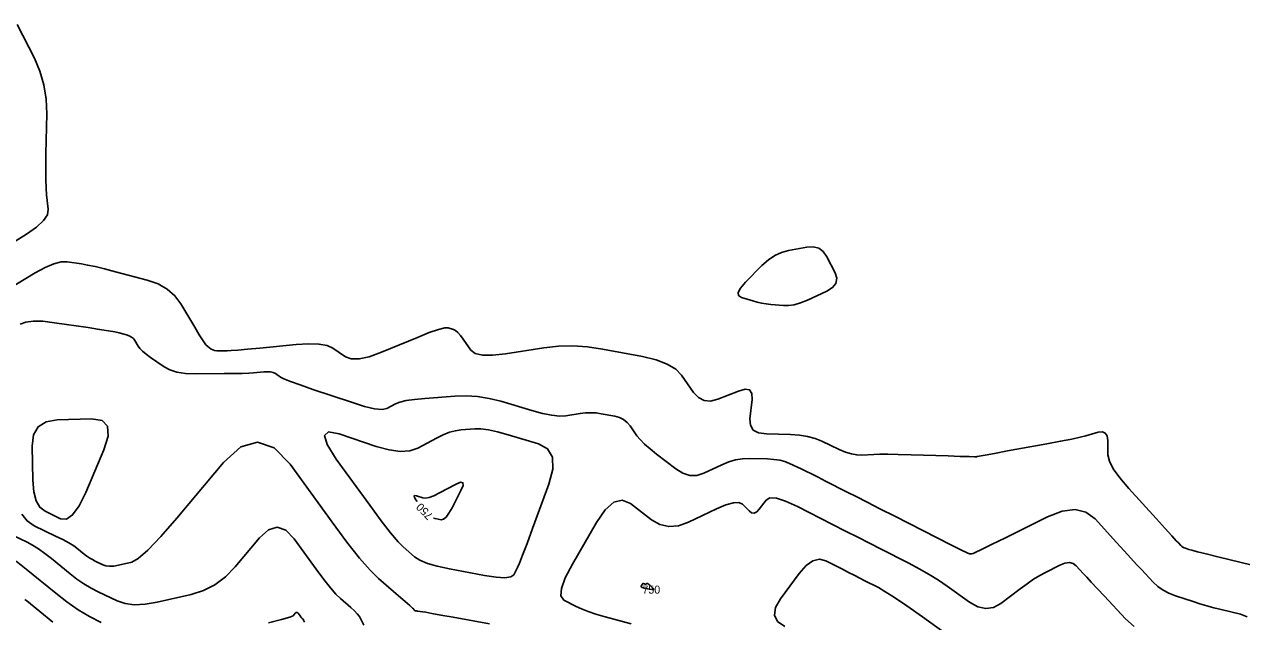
# Model space of a CAD drawing. Extents: x 2082232 to 2083549, y 592624 to 593832.
# Drawn here: x 2082625.4 to 2082731.8, y 592716.1 to 592768.3 of the extents above; entities that cross this region are included whole.
import ezdxf

# ---------------------------------------------------------------- set-up
doc = ezdxf.new("R2010")
doc.units = 0
doc.layers.add('DT_X_Contour_Major', color=7, linetype='Continuous')
doc.layers.add('DT_X_Contour_Minor', color=7, linetype='Continuous')

msp = doc.modelspace()

# ---------------------------------------------------------------- linework, layer by layer
at = {"layer": 'DT_X_Contour_Major'}
for points in [[(2082663.54, 592727.55), (2082663.73, 592728), (2082663.71, 592728.24), (2082663.49, 592728.28), (2082663.06, 592728.1), (2082661.66, 592727.35), (2082661.18, 592727.11), (2082660.77, 592726.96), (2082660.44, 592726.9), (2082660.2, 592726.92), (2082659.65, 592727.11), (2082659.49, 592727.14), (2082659.44, 592727.08), (2082659.47, 592726.95), (2082659.61, 592726.74), (2082659.71, 592726.6)], [(2082661.14, 592725.14), (2082661.28, 592725.11), (2082661.8, 592725.01), (2082662.01, 592725.05), (2082662.24, 592725.24), (2082662.49, 592725.58), (2082662.77, 592726.06), (2082663.54, 592727.55)], [(2082707.89, 592713.68), (2082703.91, 592716.51), (2082702.55, 592717.47), (2082701.46, 592718.21), (2082700.62, 592718.75), (2082700.05, 592719.08), (2082698.87, 592719.68), (2082698.42, 592719.91), (2082697.94, 592720.16), (2082697.44, 592720.41), (2082696.9, 592720.68), (2082695.45, 592721.42), (2082694.9, 592721.56), (2082694.33, 592721.42), (2082693.74, 592721), (2082693.13, 592720.31), (2082691.48, 592718.1), (2082691.04, 592717.33), (2082690.96, 592716.67), (2082691.23, 592716.12), (2082691.86, 592715.68)], [(2082680.23, 592718.9), (2082680.34, 592718.88), (2082680.39, 592718.9), (2082680.38, 592718.95), (2082680.32, 592719.03), (2082680.07, 592719.28), (2082679.98, 592719.36), (2082679.91, 592719.41), (2082679.85, 592719.44), (2082679.81, 592719.44), (2082679.72, 592719.39), (2082679.68, 592719.38), (2082679.65, 592719.38), (2082679.62, 592719.38), (2082679.59, 592719.4), (2082679.52, 592719.45), (2082679.49, 592719.46), (2082679.47, 592719.46), (2082679.44, 592719.43), (2082679.41, 592719.39), (2082679.33, 592719.25), (2082679.3, 592719.21), (2082679.29, 592719.17), (2082679.29, 592719.15), (2082679.3, 592719.13), (2082679.34, 592719.11), (2082679.36, 592719.1), (2082679.38, 592719.09), (2082679.41, 592719.09), (2082679.44, 592719.08), (2082679.52, 592719.05), (2082679.57, 592719.04), (2082679.64, 592719.02), (2082679.74, 592719), (2082679.86, 592718.98), (2082680.23, 592718.9)], [(2082625.41, 592718.04), (2082625.56, 592717.92), (2082627.84, 592716.07)]]:
    msp.add_lwpolyline(points, dxfattribs=at)
at = {"layer": 'DT_X_Contour_Minor'}
for points in [[(2082624.73, 592768.3), (2082626.23, 592765.34), (2082626.72, 592764.2), (2082627.07, 592763.01), (2082627.26, 592761.77), (2082627.31, 592760.49), (2082627.24, 592756.99), (2082627.23, 592755.78), (2082627.23, 592754.78), (2082627.26, 592753.99), (2082627.3, 592753.42), (2082627.45, 592752.16), (2082627.37, 592751.67), (2082627.03, 592751.15), (2082626.42, 592750.58), (2082625.55, 592749.98), (2082622.86, 592748.32)], [(2082688.08, 592744.44), (2082687.82, 592744.6), (2082687.79, 592744.88), (2082687.99, 592745.26), (2082688.42, 592745.76), (2082689.87, 592747.22), (2082690.43, 592747.72), (2082690.99, 592748.1), (2082691.58, 592748.38), (2082692.18, 592748.54), (2082693.79, 592748.83), (2082694.36, 592748.86), (2082694.83, 592748.73), (2082695.23, 592748.45), (2082695.54, 592748), (2082696.26, 592746.6), (2082696.41, 592746.11), (2082696.34, 592745.67), (2082696.05, 592745.3), (2082695.53, 592744.98), (2082693.84, 592744.21), (2082693.24, 592743.96), (2082692.69, 592743.8), (2082692.2, 592743.72), (2082691.75, 592743.72), (2082690.65, 592743.83), (2082690.24, 592743.88), (2082689.84, 592743.95), (2082689.46, 592744.03), (2082689.08, 592744.13), (2082688.08, 592744.44)], [(2082732.75, 592721.03), (2082729.73, 592721.77), (2082728.72, 592722.02), (2082727.97, 592722.21), (2082727.47, 592722.34), (2082727.22, 592722.4), (2082726.9, 592722.51), (2082726.79, 592722.55), (2082726.68, 592722.61), (2082726.59, 592722.68), (2082726.5, 592722.75), (2082726.29, 592722.98), (2082726.11, 592723.17), (2082725.73, 592723.6), (2082725.13, 592724.24), (2082724.34, 592725.12), (2082721.95, 592727.75), (2082721.16, 592728.67), (2082720.6, 592729.47), (2082720.26, 592730.13), (2082720.13, 592730.67), (2082720.11, 592731.93), (2082720.05, 592732.33), (2082719.89, 592732.58), (2082719.64, 592732.69), (2082719.28, 592732.65), (2082718.21, 592732.35), (2082717.69, 592732.22), (2082716.96, 592732.06), (2082715.99, 592731.87), (2082714.8, 592731.65), (2082711.34, 592731.02), (2082710.2, 592730.81), (2082709.38, 592730.66), (2082708.88, 592730.57), (2082708.7, 592730.53), (2082708.64, 592730.52), (2082708.46, 592730.52), (2082707.99, 592730.53), (2082707.22, 592730.55), (2082706.16, 592730.58), (2082702.91, 592730.68), (2082701.79, 592730.71), (2082700.88, 592730.73), (2082700.17, 592730.73), (2082699.66, 592730.71), (2082698.58, 592730.66), (2082698.16, 592730.67), (2082697.69, 592730.76), (2082697.18, 592730.92), (2082696.63, 592731.15), (2082695.11, 592731.88), (2082694.51, 592732.11), (2082693.86, 592732.29), (2082693.15, 592732.4), (2082692.38, 592732.45), (2082690.26, 592732.51), (2082689.58, 592732.6), (2082689.11, 592732.85), (2082688.86, 592733.26), (2082688.82, 592733.82), (2082689.01, 592735.52), (2082688.99, 592736.05), (2082688.78, 592736.35), (2082688.39, 592736.42), (2082687.81, 592736.26), (2082686.01, 592735.54), (2082685.37, 592735.38), (2082684.81, 592735.42), (2082684.31, 592735.68), (2082683.88, 592736.14), (2082682.84, 592737.65), (2082682.33, 592738.17), (2082681.59, 592738.62), (2082680.62, 592738.99), (2082679.43, 592739.27), (2082675.93, 592739.93), (2082674.62, 592740.12), (2082673.33, 592740.2), (2082672.06, 592740.17), (2082670.79, 592740.03), (2082667.44, 592739.51), (2082666.31, 592739.38), (2082665.43, 592739.39), (2082664.8, 592739.55), (2082664.42, 592739.84), (2082663.75, 592740.8), (2082663.5, 592741.12), (2082663.28, 592741.37), (2082663.07, 592741.54), (2082662.89, 592741.64), (2082662.42, 592741.79), (2082662.12, 592741.78), (2082661.57, 592741.64), (2082660.77, 592741.36), (2082659.73, 592740.94), (2082656.6, 592739.65), (2082655.52, 592739.26), (2082654.64, 592739.06), (2082653.94, 592739.06), (2082653.43, 592739.25), (2082652.34, 592740), (2082651.83, 592740.23), (2082651.12, 592740.36), (2082650.22, 592740.39), (2082649.13, 592740.32), (2082645.95, 592740.01), (2082644.88, 592739.91), (2082644.04, 592739.84), (2082643.44, 592739.79), (2082643.08, 592739.78), (2082642.42, 592739.77), (2082642.19, 592739.78), (2082641.99, 592739.81), (2082641.83, 592739.86), (2082641.7, 592739.93), (2082641.39, 592740.15), (2082641.23, 592740.31), (2082640.99, 592740.65), (2082640.66, 592741.16), (2082640.26, 592741.84), (2082639.05, 592743.89), (2082638.53, 592744.59), (2082637.86, 592745.17), (2082637.05, 592745.63), (2082636.09, 592745.96), (2082633.34, 592746.69), (2082632.38, 592746.93), (2082631.56, 592747.13), (2082630.88, 592747.27), (2082630.34, 592747.37), (2082629.09, 592747.55), (2082628.57, 592747.54), (2082627.93, 592747.38), (2082627.18, 592747.06), (2082626.31, 592746.58), (2082623.85, 592745.1)], [(2082624.99, 592742.09), (2082625.48, 592742.27), (2082626.14, 592742.36), (2082626.97, 592742.35), (2082627.99, 592742.23), (2082630.93, 592741.8), (2082631.93, 592741.65), (2082632.71, 592741.52), (2082633.28, 592741.42), (2082633.64, 592741.34), (2082634.3, 592741.17), (2082634.53, 592741.09), (2082634.73, 592740.98), (2082634.89, 592740.84), (2082635.01, 592740.67), (2082635.3, 592740.18), (2082635.45, 592739.98), (2082635.68, 592739.74), (2082636, 592739.48), (2082636.4, 592739.19), (2082637.57, 592738.38), (2082638.08, 592738.11), (2082638.7, 592737.92), (2082639.46, 592737.8), (2082640.33, 592737.77), (2082642.84, 592737.78), (2082643.7, 592737.78), (2082644.41, 592737.8), (2082644.98, 592737.82), (2082645.39, 592737.85), (2082646.3, 592737.94), (2082646.62, 592737.95), (2082646.89, 592737.93), (2082647.12, 592737.87), (2082647.31, 592737.78), (2082647.75, 592737.48), (2082648.05, 592737.33), (2082648.63, 592737.1), (2082649.48, 592736.79), (2082650.6, 592736.4), (2082653.96, 592735.27), (2082655.1, 592734.92), (2082655.99, 592734.71), (2082656.64, 592734.65), (2082657.05, 592734.73), (2082657.83, 592735.15), (2082658.2, 592735.29), (2082658.75, 592735.42), (2082659.48, 592735.52), (2082660.38, 592735.61), (2082663.01, 592735.81), (2082664, 592735.84), (2082665, 592735.77), (2082666, 592735.61), (2082667.02, 592735.36), (2082669.73, 592734.55), (2082670.68, 592734.3), (2082671.49, 592734.14), (2082672.17, 592734.07), (2082672.71, 592734.1), (2082673.97, 592734.29), (2082674.44, 592734.35), (2082674.9, 592734.36), (2082675.36, 592734.34), (2082675.8, 592734.27), (2082676.99, 592734.05), (2082677.41, 592733.93), (2082677.77, 592733.76), (2082678.08, 592733.52), (2082678.34, 592733.23), (2082678.94, 592732.35), (2082679.22, 592732.01), (2082679.6, 592731.62), (2082680.08, 592731.2), (2082680.65, 592730.74), (2082682.33, 592729.46), (2082682.95, 592729.07), (2082683.57, 592728.88), (2082684.18, 592728.88), (2082684.78, 592729.07), (2082686.37, 592729.82), (2082686.97, 592730.06), (2082687.56, 592730.24), (2082688.16, 592730.33), (2082688.75, 592730.35), (2082690.34, 592730.32), (2082690.91, 592730.28), (2082691.43, 592730.21), (2082691.88, 592730.09), (2082692.29, 592729.93), (2082693.29, 592729.46), (2082693.7, 592729.26), (2082694.2, 592729.01), (2082694.78, 592728.72), (2082695.44, 592728.39), (2082697.32, 592727.43), (2082698.11, 592727.03), (2082699.06, 592726.55), (2082700.19, 592725.97), (2082701.49, 592725.31), (2082705.18, 592723.43), (2082706.39, 592722.82), (2082707.27, 592722.38), (2082707.81, 592722.11), (2082708.01, 592722.03), (2082708.11, 592722.02), (2082708.14, 592722.02), (2082708.18, 592722.03), (2082708.21, 592722.03), (2082708.24, 592722.03), (2082708.33, 592722.05), (2082708.53, 592722.14), (2082709.07, 592722.4), (2082709.95, 592722.83), (2082711.16, 592723.43), (2082714.83, 592725.26), (2082716.13, 592725.76), (2082717.25, 592725.9), (2082718.21, 592725.68), (2082719, 592725.08), (2082720.88, 592723.02), (2082721.54, 592722.29), (2082722.13, 592721.65), (2082722.63, 592721.1), (2082723.06, 592720.65), (2082724.09, 592719.56), (2082724.5, 592719.18), (2082724.96, 592718.85), (2082725.47, 592718.58), (2082726.03, 592718.36), (2082727.59, 592717.85), (2082728.18, 592717.67), (2082728.79, 592717.49), (2082729.4, 592717.32), (2082730.03, 592717.16), (2082731.72, 592716.75), (2082732.32, 592716.52)], [(2082626.04, 592731.44), (2082626.16, 592732.43), (2082626.57, 592733.14), (2082627.26, 592733.57), (2082628.24, 592733.74), (2082631.24, 592733.83), (2082632.15, 592733.68), (2082632.63, 592733.18), (2082632.68, 592732.32), (2082632.31, 592731.11), (2082630.72, 592727.4), (2082630.14, 592726.21), (2082629.58, 592725.43), (2082629.04, 592725.06), (2082628.52, 592725.1), (2082627.17, 592725.75), (2082626.72, 592726.1), (2082626.39, 592726.67), (2082626.19, 592727.46), (2082626.1, 592728.47), (2082626.04, 592731.44)], [(2082665.6, 592720.14), (2082666.63, 592719.98), (2082667.39, 592719.94), (2082667.9, 592720.01), (2082668.16, 592720.19), (2082668.48, 592720.82), (2082668.66, 592721.21), (2082668.94, 592721.91), (2082669.32, 592722.92), (2082669.8, 592724.23), (2082671.24, 592728.13), (2082671.58, 592729.44), (2082671.55, 592730.47), (2082671.12, 592731.2), (2082670.32, 592731.64), (2082667.66, 592732.43), (2082666.73, 592732.69), (2082665.94, 592732.86), (2082665.28, 592732.95), (2082664.75, 592732.96), (2082663.54, 592732.86), (2082663.06, 592732.79), (2082662.55, 592732.65), (2082661.99, 592732.43), (2082661.4, 592732.14), (2082659.77, 592731.26), (2082659.08, 592731.02), (2082658.24, 592730.97), (2082657.25, 592731.11), (2082656.12, 592731.42), (2082652.88, 592732.51), (2082651.95, 592732.68), (2082651.61, 592732.37), (2082651.84, 592731.58), (2082652.64, 592730.31), (2082655.57, 592726.28), (2082656.57, 592724.92), (2082657.39, 592723.86), (2082658.04, 592723.09), (2082658.5, 592722.63), (2082659.48, 592721.78), (2082659.95, 592721.47), (2082660.61, 592721.19), (2082661.47, 592720.94), (2082662.53, 592720.71), (2082665.6, 592720.14)], [(2082666.04, 592715.9), (2082662.85, 592716.49), (2082661.79, 592716.68), (2082660.99, 592716.82), (2082660.47, 592716.92), (2082660.21, 592716.96), (2082659.75, 592717.03), (2082659.66, 592717.04), (2082659.6, 592717.05), (2082659.57, 592717.05), (2082659.52, 592717.06), (2082659.5, 592717.07), (2082659.48, 592717.08), (2082659.47, 592717.09), (2082659.46, 592717.1), (2082659.43, 592717.14), (2082659.43, 592717.16), (2082659.42, 592717.17), (2082659.41, 592717.18), (2082659.41, 592717.19), (2082659.4, 592717.21), (2082659.31, 592717.29), (2082659.07, 592717.51), (2082658.66, 592717.86), (2082658.09, 592718.35), (2082656.34, 592719.86), (2082655.6, 592720.59), (2082654.67, 592721.65), (2082653.57, 592723.05), (2082652.28, 592724.79), (2082648.6, 592729.86), (2082647.2, 592731.29), (2082645.76, 592731.8), (2082644.29, 592731.37), (2082642.77, 592730.01), (2082638.69, 592725.14), (2082637.29, 592723.53), (2082636.17, 592722.36), (2082635.32, 592721.61), (2082634.75, 592721.3), (2082633.58, 592721.03), (2082633.17, 592720.96), (2082632.8, 592720.95), (2082632.48, 592720.98), (2082632.21, 592721.07), (2082631.56, 592721.39), (2082631.32, 592721.52), (2082631.07, 592721.66), (2082630.83, 592721.83), (2082630.6, 592722.01), (2082629.96, 592722.53), (2082629.67, 592722.74), (2082629.25, 592722.98), (2082628.73, 592723.27), (2082628.08, 592723.58), (2082626.2, 592724.48), (2082625.59, 592724.9), (2082625.14, 592725.5)], [(2082722.41, 592715.68), (2082721.68, 592716.36), (2082719.83, 592718.32), (2082719.19, 592718.99), (2082718.67, 592719.55), (2082718.27, 592719.98), (2082717.97, 592720.3), (2082717.35, 592720.99), (2082717.08, 592721.18), (2082716.76, 592721.26), (2082716.37, 592721.2), (2082715.93, 592721.03), (2082714.66, 592720.4), (2082714.16, 592720.13), (2082713.63, 592719.8), (2082713.06, 592719.42), (2082712.45, 592718.97), (2082710.77, 592717.7), (2082710.12, 592717.35), (2082709.45, 592717.25), (2082708.75, 592717.4), (2082708.03, 592717.8), (2082706.06, 592719.2), (2082705.3, 592719.72), (2082704.49, 592720.23), (2082703.63, 592720.72), (2082702.72, 592721.2), (2082700.23, 592722.47), (2082699.27, 592722.96), (2082698.25, 592723.48), (2082697.18, 592724.02), (2082696.05, 592724.6), (2082692.98, 592726.16), (2082691.94, 592726.63), (2082691.14, 592726.89), (2082690.57, 592726.92), (2082690.23, 592726.73), (2082689.63, 592725.93), (2082689.41, 592725.7), (2082689.19, 592725.59), (2082688.96, 592725.62), (2082688.74, 592725.78), (2082688.16, 592726.37), (2082687.85, 592726.51), (2082687.37, 592726.49), (2082686.71, 592726.3), (2082685.89, 592725.95), (2082683.45, 592724.8), (2082682.56, 592724.48), (2082681.72, 592724.41), (2082680.94, 592724.58), (2082680.22, 592725), (2082678.36, 592726.42), (2082677.65, 592726.71), (2082676.92, 592726.54), (2082676.17, 592725.88), (2082675.39, 592724.76), (2082673.31, 592721.13), (2082672.67, 592719.92), (2082672.33, 592718.99), (2082672.29, 592718.35), (2082672.55, 592717.99), (2082673.63, 592717.42), (2082674.09, 592717.21), (2082674.67, 592716.99), (2082675.35, 592716.76), (2082676.15, 592716.53), (2082678.44, 592715.91)], [(2082624.37, 592723.62), (2082625.6, 592723.04), (2082626.08, 592722.78), (2082626.6, 592722.46), (2082627.15, 592722.07), (2082627.74, 592721.61), (2082629.35, 592720.29), (2082629.96, 592719.82), (2082630.57, 592719.4), (2082631.19, 592719.03), (2082631.81, 592718.71), (2082633.48, 592717.91), (2082634.16, 592717.68), (2082634.97, 592717.58), (2082635.91, 592717.62), (2082636.96, 592717.81), (2082639.94, 592718.47), (2082641.02, 592718.81), (2082642.02, 592719.32), (2082642.94, 592720.01), (2082643.78, 592720.88), (2082645.91, 592723.42), (2082646.7, 592724.13), (2082647.47, 592724.36), (2082648.22, 592724.09), (2082648.95, 592723.34), (2082650.88, 592720.69), (2082651.55, 592719.79), (2082652.13, 592719.06), (2082652.61, 592718.5), (2082653, 592718.12), (2082653.91, 592717.33), (2082654.22, 592717.05), (2082654.47, 592716.79), (2082654.66, 592716.55), (2082654.78, 592716.33), (2082655.04, 592715.78)], [(2082624.63, 592721.4), (2082625.51, 592720.69), (2082628.11, 592718.58), (2082629.08, 592717.82), (2082630.07, 592717.14), (2082631.06, 592716.55), (2082632.06, 592716.02)], [(2082646.71, 592716.01), (2082647.86, 592716.29), (2082648.58, 592716.49), (2082648.86, 592716.61), (2082649.05, 592716.83), (2082649.11, 592716.89), (2082649.18, 592716.91), (2082649.25, 592716.89), (2082649.31, 592716.83), (2082649.47, 592716.6), (2082649.53, 592716.52), (2082649.58, 592716.46), (2082649.62, 592716.41), (2082649.66, 592716.38), (2082649.74, 592716.31), (2082649.78, 592716.24), (2082649.87, 592716.07)]]:
    msp.add_lwpolyline(points, dxfattribs=at)

# ---------------------------------------------------------------- texts
at = {"layer": 'DT_X_Contour_Major'}
msp.add_text('750', height=0.7, rotation=134.4801, dxfattribs=at).set_placement((2082661.15, 592725.42))
msp.add_text('750', height=0.7, dxfattribs=at).set_placement((2082679.41, 592718.55))

doc.saveas('drawing.dxf')
